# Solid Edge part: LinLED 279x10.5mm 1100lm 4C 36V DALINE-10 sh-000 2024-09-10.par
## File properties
Author: robert.pupel
Template: iso metric part.par
Last saved by: robert.pupel
Revision: 2
Application: Solid Edge
Gęstość: 0.000 kg/m^3
Dokładność: 0.990
Username: robert.pupel
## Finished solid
Body 1: solid body, 727 faces, 1970 edges, 1310 vertices.
  Faces by surface: plane 670, cylinder 57
  Edges by curve: line 1656, spline 164, circle 86, curve on surface 64
Bounding box of the edges (mm): 279.000 x 3.600 x 10.500, from (-139.5, -2, -5.25) to (139.5, 1.6, 5.25).
Cylindrical faces by radius (mm): R0.4 x24, R0.6 x8, R0.8 x8, R1 x1, R1.5309 x4, R1.5312 x4, R1.7414 x4, R1.7423 x4
Planar faces by outward normal: +x 79, +y 29, +z 77, -x 79, -y 121, -z 77, oblique 208
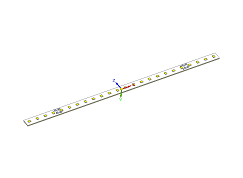
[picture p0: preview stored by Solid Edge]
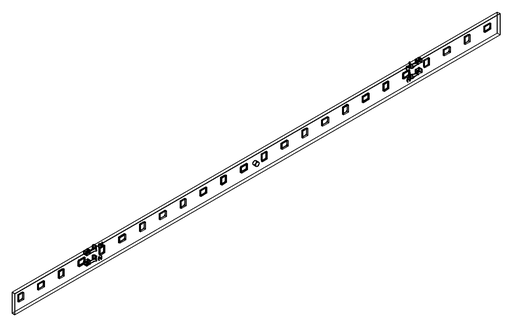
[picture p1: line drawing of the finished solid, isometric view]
